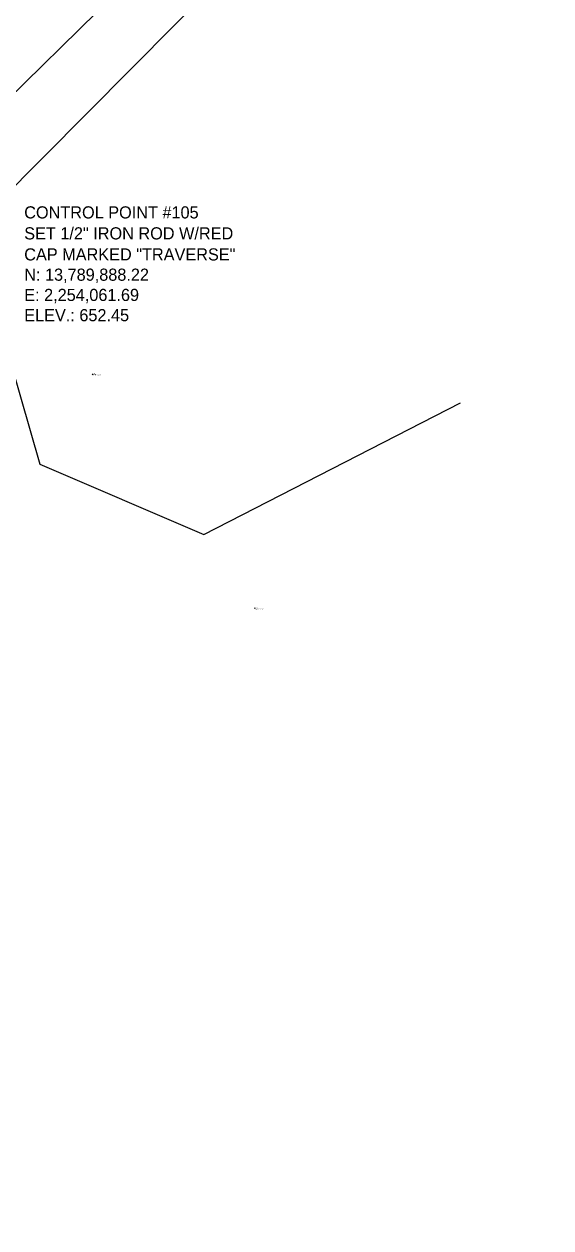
# Model space of a CAD drawing. Extents: x 2250985 to 2256614, y 13788357 to 13792478.
# Drawn here: x 2254074 to 2254126, y 13789776 to 13789894.9 of the extents above; entities that cross this region are included whole.
import ezdxf

# ---------------------------------------------------------------- set-up
doc = ezdxf.new("R2010")
doc.units = 0
for name, color, linetype in [('E_Control_Control Point See GPS AZM_CP_ANNO', 7, 'Continuous'), ('E_DTM_Grade Break_GB', 7, 'Continuous'), ('E_DTM_Natural Ground_NG', 7, 'Continuous'), ('E_DTM_Natural Ground_NG_Description', 7, 'Continuous'), ('E_DTM_Natural Ground_NG_Elevation', 7, 'Continuous'), ('E_DTM_Natural Ground_NG_point', 7, 'Continuous'), ('E_Utility_Water_Water Line_WL', 7, 'Continuous'), ('Minor Contours', 7, 'Continuous')]:
    doc.layers.add(name, color=color, linetype=linetype)

# ---------------------------------------------------------------- blocks, each defined once
blk = doc.blocks.new('NG')
at = {"layer": 'E_DTM_Natural Ground_NG'}
for p in [(-0.07, 0.09), (-0.07, -0.09), (0.07, 0.09), (0.07, -0.09)]:
    blk.add_line(p, (0, 0), dxfattribs=at)

msp = doc.modelspace()

# ---------------------------------------------------------------- linework, layer by layer
at = {"layer": 'E_DTM_Grade Break_GB'}
msp.add_lwpolyline([(2254057.29, 13789871.24), (2254063.29, 13789878.54), (2254111.58, 13789925.98), (2254185.81, 13790003.22), (2254253.26, 13790074.98)], dxfattribs=at)
at = {"layer": 'E_Utility_Water_Water Line_WL'}
msp.add_lwpolyline([(2253509.01, 13789307.27), (2253682.68, 13789482.53), (2253716.7, 13789517.37), (2253844.09, 13789647.68), (2253874.13, 13789677.94), (2254034.25, 13789841.09), (2254062.75, 13789868.53), (2254262.93, 13790070.34), (2254312.5, 13790122.89), (2254343.76, 13790154.03), (2254421.83, 13790230.79), (2254511.68, 13790322.46), (2254595.44, 13790408.28), (2254708.71, 13790523.29), (2254783.64, 13790598.93), (2254863.02, 13790680.5), (2254955.98, 13790777.48), (2254983.99, 13790796.95)], dxfattribs=at)
at = {"layer": 'Minor Contours'}
msp.add_lwpolyline([(2254074.6, 13789918.66), (2254062.8, 13789903.73), (2254050.46, 13789889.67), (2254051.52, 13789884.11), (2254061.34, 13789880.06), (2254067.98, 13789885.2), (2254073.05, 13789888.13), (2254070.73, 13789885.21), (2254068.64, 13789877.57), (2254068.12, 13789873.08), (2254071.77, 13789864.48), (2254075.52, 13789851.42), (2254091.69, 13789844.49), (2254117.03, 13789857.46)], dxfattribs=at)

# ---------------------------------------------------------------- block references
at = {"layer": 'E_DTM_Natural Ground_NG', "xscale": 0.5, "yscale": 0.5}
for p in [(2254080.74, 13789860.3), (2254096.74, 13789837.2)]:
    msp.add_blockref('NG', p, dxfattribs=at)

# ---------------------------------------------------------------- texts
at = {"layer": 'E_Control_Control Point See GPS AZM_CP_ANNO'}
for s, p in [('CONTROL POINT #105', (2254073.98, 13789875.68)), ('SET 1/2" IRON ROD W/RED ', (2254073.98, 13789873.61)), ('CAP MARKED "TRAVERSE"', (2254073.98, 13789871.53)), ('N: 13,789,888.22', (2254073.98, 13789869.53)), ('E: 2,254,061.69', (2254073.98, 13789867.53)), ('ELEV.: 652.45', (2254073.98, 13789865.53))]:
    msp.add_text(s, height=1.2, dxfattribs=at).set_placement(p)
at = {"layer": 'E_DTM_Natural Ground_NG_Description'}
for p in [(2254080.8, 13789860.18), (2254096.8, 13789837.08)]:
    msp.add_text('NATURAL GROUND', height=0.06, dxfattribs=at).set_placement(p)
at = {"layer": 'E_DTM_Natural Ground_NG_Elevation'}
for s, p in [('652.61', (2254080.8, 13789860.27)), ('653.18', (2254096.8, 13789837.17))]:
    msp.add_text(s, height=0.06, dxfattribs=at).set_placement(p)
at = {"layer": 'E_DTM_Natural Ground_NG_point'}
for s, p in [('6375', (2254080.8, 13789860.36)), ('6700', (2254096.8, 13789837.26))]:
    msp.add_text(s, height=0.06, dxfattribs=at).set_placement(p)

doc.saveas('drawing.dxf')
